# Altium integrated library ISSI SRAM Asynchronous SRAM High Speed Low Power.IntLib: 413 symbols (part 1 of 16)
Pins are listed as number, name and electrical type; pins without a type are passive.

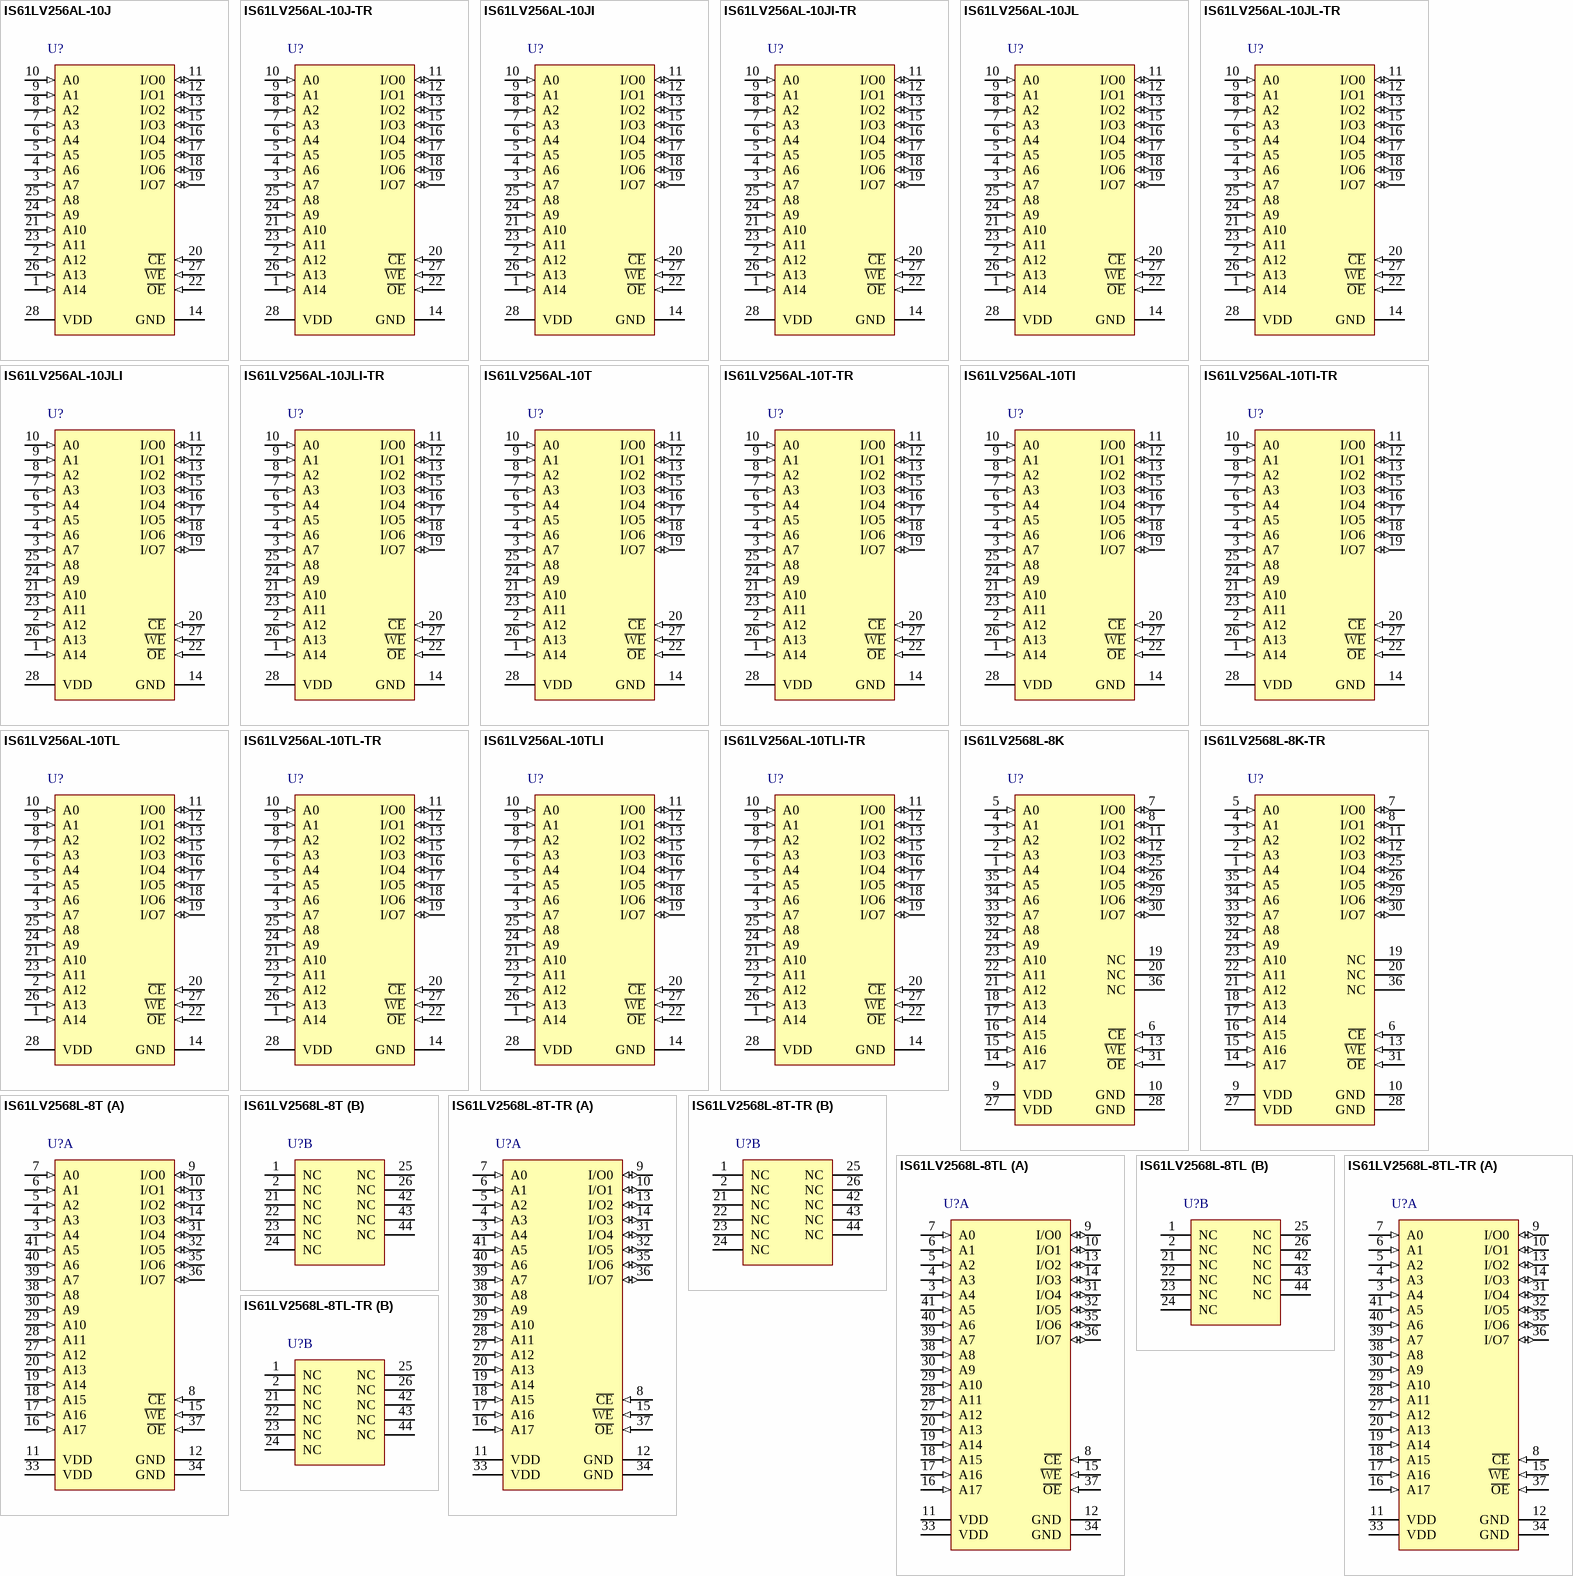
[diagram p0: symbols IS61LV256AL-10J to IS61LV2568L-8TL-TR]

## IS61LV256AL-10J
designator U?
256 K Low Voltage CMOS SRAM, 32 K x 8, 0 to 70 degC, 28-Pin SOJ (SOJ-28); Manufacturer: Integrated Silicon Solution Inc (ISSI); PartNumber: IS61LV256AL-10J; Density: 256K; Organization: 32K x 8; Packing: Tray / Tube; Speed (ns): 10
footprint ISSI-SOJ-28_A_N (SOJ, 28-Leads, Body 18.54x7.75mm, Pitch 1.27mm, IPC Medium Density)
pins: 1 A14 (in) "Address Inputs", 2 A12 (in) "Address Inputs", 3 A7 (in) "Address Inputs", 4 A6 (in) "Address Inputs", 5 A5 (in) "Address Inputs", 6 A4 (in) "Address Inputs", 7 A3 (in) "Address Inputs", 8 A2 (in) "Address Inputs", 9 A1 (in) "Address Inputs", 10 A0 (in) "Address Inputs", 11 I/O0 (io) "Input/Output", 12 I/O1 (io) "Input/Output", 13 I/O2 (io) "Input/Output", 14 GND (power) "Ground", 15 I/O3 (io) "Input/Output", 16 I/O4 (io) "Input/Output", 17 I/O5 (io) "Input/Output", 18 I/O6 (io) "Input/Output", 19 I/O7 (io) "Input/Output", 20 ~{CE} (in) "Chip Enable Input", 21 A10 (in) "Address Inputs", 22 ~{OE} (in) "Output Enable Input", 23 A11 (in) "Address Inputs", 24 A9 (in) "Address Inputs", 25 A8 (in) "Address Inputs", 26 A13 (in) "Address Inputs", 27 ~{WE} (in) "Write Enable Input", 28 VDD (power) "Power"

## IS61LV256AL-10J-TR
designator U?
256 K Low Voltage CMOS SRAM, 32 K x 8, 0 to 70 degC, 28-Pin SOJ (SOJ-28_A); Manufacturer: Integrated Silicon Solution Inc (ISSI); PartNumber: IS61LV256AL-10J-TR; Density: 256K; Organization: 32K x 8; Packing: Tape & Reel; Speed (ns): 10
footprint ISSI-SOJ-28_A_N (SOJ, 28-Leads, Body 18.54x7.75mm, Pitch 1.27mm, IPC Medium Density)
pins: 1 A14 (in) "Address Inputs", 2 A12 (in) "Address Inputs", 3 A7 (in) "Address Inputs", 4 A6 (in) "Address Inputs", 5 A5 (in) "Address Inputs", 6 A4 (in) "Address Inputs", 7 A3 (in) "Address Inputs", 8 A2 (in) "Address Inputs", 9 A1 (in) "Address Inputs", 10 A0 (in) "Address Inputs", 11 I/O0 (io) "Input/Output", 12 I/O1 (io) "Input/Output", 13 I/O2 (io) "Input/Output", 14 GND (power) "Ground", 15 I/O3 (io) "Input/Output", 16 I/O4 (io) "Input/Output", 17 I/O5 (io) "Input/Output", 18 I/O6 (io) "Input/Output", 19 I/O7 (io) "Input/Output", 20 ~{CE} (in) "Chip Enable Input", 21 A10 (in) "Address Inputs", 22 ~{OE} (in) "Output Enable Input", 23 A11 (in) "Address Inputs", 24 A9 (in) "Address Inputs", 25 A8 (in) "Address Inputs", 26 A13 (in) "Address Inputs", 27 ~{WE} (in) "Write Enable Input", 28 VDD (power) "Power"

## IS61LV256AL-10JI
designator U?
256 K Low Voltage CMOS SRAM, 32 K x 8, -40 to 85 degC, 28-Pin SOJ (SOJ-28); Manufacturer: Integrated Silicon Solution Inc (ISSI); PartNumber: IS61LV256AL-10JI; Density: 256K; Organization: 32K x 8; Packing: Tray / Tube; Speed (ns): 10
footprint ISSI-SOJ-28_A_N (SOJ, 28-Leads, Body 18.54x7.75mm, Pitch 1.27mm, IPC Medium Density)
pins: 1 A14 (in) "Address Inputs", 2 A12 (in) "Address Inputs", 3 A7 (in) "Address Inputs", 4 A6 (in) "Address Inputs", 5 A5 (in) "Address Inputs", 6 A4 (in) "Address Inputs", 7 A3 (in) "Address Inputs", 8 A2 (in) "Address Inputs", 9 A1 (in) "Address Inputs", 10 A0 (in) "Address Inputs", 11 I/O0 (io) "Input/Output", 12 I/O1 (io) "Input/Output", 13 I/O2 (io) "Input/Output", 14 GND (power) "Ground", 15 I/O3 (io) "Input/Output", 16 I/O4 (io) "Input/Output", 17 I/O5 (io) "Input/Output", 18 I/O6 (io) "Input/Output", 19 I/O7 (io) "Input/Output", 20 ~{CE} (in) "Chip Enable Input", 21 A10 (in) "Address Inputs", 22 ~{OE} (in) "Output Enable Input", 23 A11 (in) "Address Inputs", 24 A9 (in) "Address Inputs", 25 A8 (in) "Address Inputs", 26 A13 (in) "Address Inputs", 27 ~{WE} (in) "Write Enable Input", 28 VDD (power) "Power"

## IS61LV256AL-10JI-TR
designator U?
256 K Low Voltage CMOS SRAM, 32 K x 8, -40 to 85 degC, 28-Pin SOJ (SOJ-28_A); Manufacturer: Integrated Silicon Solution Inc (ISSI); PartNumber: IS61LV256AL-10JI-TR; Density: 256K; Organization: 32K x 8; Packing: Tape & Reel; Speed (ns): 10
footprint ISSI-SOJ-28_A_N (SOJ, 28-Leads, Body 18.54x7.75mm, Pitch 1.27mm, IPC Medium Density)
pins: 1 A14 (in) "Address Inputs", 2 A12 (in) "Address Inputs", 3 A7 (in) "Address Inputs", 4 A6 (in) "Address Inputs", 5 A5 (in) "Address Inputs", 6 A4 (in) "Address Inputs", 7 A3 (in) "Address Inputs", 8 A2 (in) "Address Inputs", 9 A1 (in) "Address Inputs", 10 A0 (in) "Address Inputs", 11 I/O0 (io) "Input/Output", 12 I/O1 (io) "Input/Output", 13 I/O2 (io) "Input/Output", 14 GND (power) "Ground", 15 I/O3 (io) "Input/Output", 16 I/O4 (io) "Input/Output", 17 I/O5 (io) "Input/Output", 18 I/O6 (io) "Input/Output", 19 I/O7 (io) "Input/Output", 20 ~{CE} (in) "Chip Enable Input", 21 A10 (in) "Address Inputs", 22 ~{OE} (in) "Output Enable Input", 23 A11 (in) "Address Inputs", 24 A9 (in) "Address Inputs", 25 A8 (in) "Address Inputs", 26 A13 (in) "Address Inputs", 27 ~{WE} (in) "Write Enable Input", 28 VDD (power) "Power"

## IS61LV256AL-10JL
designator U?
256 K Low Voltage CMOS SRAM, 32 K x 8, 0 to 70 degC, 28-Pin SOJ (SOJ-28), Pb-Free; Manufacturer: Integrated Silicon Solution Inc (ISSI); PartNumber: IS61LV256AL-10JL; Density: 256K; Organization: 32K x 8; Packing: Tray / Tube; Speed (ns): 10
footprint ISSI-SOJ-28_A_N (SOJ, 28-Leads, Body 18.54x7.75mm, Pitch 1.27mm, IPC Medium Density)
pins: 1 A14 (in) "Address Inputs", 2 A12 (in) "Address Inputs", 3 A7 (in) "Address Inputs", 4 A6 (in) "Address Inputs", 5 A5 (in) "Address Inputs", 6 A4 (in) "Address Inputs", 7 A3 (in) "Address Inputs", 8 A2 (in) "Address Inputs", 9 A1 (in) "Address Inputs", 10 A0 (in) "Address Inputs", 11 I/O0 (io) "Input/Output", 12 I/O1 (io) "Input/Output", 13 I/O2 (io) "Input/Output", 14 GND (power) "Ground", 15 I/O3 (io) "Input/Output", 16 I/O4 (io) "Input/Output", 17 I/O5 (io) "Input/Output", 18 I/O6 (io) "Input/Output", 19 I/O7 (io) "Input/Output", 20 ~{CE} (in) "Chip Enable Input", 21 A10 (in) "Address Inputs", 22 ~{OE} (in) "Output Enable Input", 23 A11 (in) "Address Inputs", 24 A9 (in) "Address Inputs", 25 A8 (in) "Address Inputs", 26 A13 (in) "Address Inputs", 27 ~{WE} (in) "Write Enable Input", 28 VDD (power) "Power"

## IS61LV256AL-10JL-TR
designator U?
256 K Low Voltage CMOS SRAM, 32 K x 8, 0 to 70 degC, 28-Pin SOJ (SOJ-28_A), Pb-Free; Manufacturer: Integrated Silicon Solution Inc (ISSI); PartNumber: IS61LV256AL-10JL-TR; Density: 256K; Organization: 32K x 8; Packing: Tape & Reel; Speed (ns): 10
footprint ISSI-SOJ-28_A_N (SOJ, 28-Leads, Body 18.54x7.75mm, Pitch 1.27mm, IPC Medium Density)
pins: 1 A14 (in) "Address Inputs", 2 A12 (in) "Address Inputs", 3 A7 (in) "Address Inputs", 4 A6 (in) "Address Inputs", 5 A5 (in) "Address Inputs", 6 A4 (in) "Address Inputs", 7 A3 (in) "Address Inputs", 8 A2 (in) "Address Inputs", 9 A1 (in) "Address Inputs", 10 A0 (in) "Address Inputs", 11 I/O0 (io) "Input/Output", 12 I/O1 (io) "Input/Output", 13 I/O2 (io) "Input/Output", 14 GND (power) "Ground", 15 I/O3 (io) "Input/Output", 16 I/O4 (io) "Input/Output", 17 I/O5 (io) "Input/Output", 18 I/O6 (io) "Input/Output", 19 I/O7 (io) "Input/Output", 20 ~{CE} (in) "Chip Enable Input", 21 A10 (in) "Address Inputs", 22 ~{OE} (in) "Output Enable Input", 23 A11 (in) "Address Inputs", 24 A9 (in) "Address Inputs", 25 A8 (in) "Address Inputs", 26 A13 (in) "Address Inputs", 27 ~{WE} (in) "Write Enable Input", 28 VDD (power) "Power"

## IS61LV256AL-10JLI
designator U?
256 K Low Voltage CMOS SRAM, 32 K x 8, -40 to 85 degC, 28-Pin SOJ (SOJ-28), Pb-Free; Manufacturer: Integrated Silicon Solution Inc (ISSI); PartNumber: IS61LV256AL-10JLI; Density: 256K; Organization: 32K x 8; Packing: Tray / Tube; Speed (ns): 10
footprint ISSI-SOJ-28_A_N (SOJ, 28-Leads, Body 18.54x7.75mm, Pitch 1.27mm, IPC Medium Density)
pins: 1 A14 (in) "Address Inputs", 2 A12 (in) "Address Inputs", 3 A7 (in) "Address Inputs", 4 A6 (in) "Address Inputs", 5 A5 (in) "Address Inputs", 6 A4 (in) "Address Inputs", 7 A3 (in) "Address Inputs", 8 A2 (in) "Address Inputs", 9 A1 (in) "Address Inputs", 10 A0 (in) "Address Inputs", 11 I/O0 (io) "Input/Output", 12 I/O1 (io) "Input/Output", 13 I/O2 (io) "Input/Output", 14 GND (power) "Ground", 15 I/O3 (io) "Input/Output", 16 I/O4 (io) "Input/Output", 17 I/O5 (io) "Input/Output", 18 I/O6 (io) "Input/Output", 19 I/O7 (io) "Input/Output", 20 ~{CE} (in) "Chip Enable Input", 21 A10 (in) "Address Inputs", 22 ~{OE} (in) "Output Enable Input", 23 A11 (in) "Address Inputs", 24 A9 (in) "Address Inputs", 25 A8 (in) "Address Inputs", 26 A13 (in) "Address Inputs", 27 ~{WE} (in) "Write Enable Input", 28 VDD (power) "Power"

## IS61LV256AL-10JLI-TR
designator U?
256 K Low Voltage CMOS SRAM, 32 K x 8, -40 to 85 degC, 28-Pin SOJ (SOJ-28_A), Pb-Free; Manufacturer: Integrated Silicon Solution Inc (ISSI); PartNumber: IS61LV256AL-10JLI-TR; Density: 256K; Organization: 32K x 8; Packing: Tape & Reel; Speed (ns): 10
footprint ISSI-SOJ-28_A_N (SOJ, 28-Leads, Body 18.54x7.75mm, Pitch 1.27mm, IPC Medium Density)
pins: 1 A14 (in) "Address Inputs", 2 A12 (in) "Address Inputs", 3 A7 (in) "Address Inputs", 4 A6 (in) "Address Inputs", 5 A5 (in) "Address Inputs", 6 A4 (in) "Address Inputs", 7 A3 (in) "Address Inputs", 8 A2 (in) "Address Inputs", 9 A1 (in) "Address Inputs", 10 A0 (in) "Address Inputs", 11 I/O0 (io) "Input/Output", 12 I/O1 (io) "Input/Output", 13 I/O2 (io) "Input/Output", 14 GND (power) "Ground", 15 I/O3 (io) "Input/Output", 16 I/O4 (io) "Input/Output", 17 I/O5 (io) "Input/Output", 18 I/O6 (io) "Input/Output", 19 I/O7 (io) "Input/Output", 20 ~{CE} (in) "Chip Enable Input", 21 A10 (in) "Address Inputs", 22 ~{OE} (in) "Output Enable Input", 23 A11 (in) "Address Inputs", 24 A9 (in) "Address Inputs", 25 A8 (in) "Address Inputs", 26 A13 (in) "Address Inputs", 27 ~{WE} (in) "Write Enable Input", 28 VDD (power) "Power"

## IS61LV256AL-10T
designator U?
256 K Low Voltage CMOS SRAM, 32 K x 8, 0 to 70 degC, 28-Pin SOP (TSOP-1-28); Manufacturer: Integrated Silicon Solution Inc (ISSI); PartNumber: IS61LV256AL-10T; Density: 256K; Organization: 32K x 8; Packing: Tray / Tube; Speed (ns): 10
footprint ISSI-TSOP-1-28-8000X13400DE_N (SOP, 28-Leads, Body 11.9x8.1mm, Pitch 0.55mm, IPC Medium Density)
pins: 1 A14 (in) "Address Input", 2 A12 (in) "Address Input", 3 A7 (in) "Address Input", 4 A6 (in) "Address Input", 5 A5 (in) "Address Input", 6 A4 (in) "Address Input", 7 A3 (in) "Address Input", 8 A2 (in) "Address Input", 9 A1 (in) "Address Input", 10 A0 (in) "Address Input", 11 I/O0 (io) "Input/Output", 12 I/O1 (io) "Input/Output", 13 I/O2 (io) "Input/Output", 14 GND (power) "Ground", 15 I/O3 (io) "Input/Output", 16 I/O4 (io) "Input/Output", 17 I/O5 (io) "Input/Output", 18 I/O6 (io) "Input/Output", 19 I/O7 (io) "Input/Output", 20 ~{CE} (in) "Chip Enable Input", 21 A10 (in) "Address Input", 22 ~{OE} (in) "Output Enable Input", 23 A11 (in) "Address Input", 24 A9 (in) "Address Input", 25 A8 (in) "Address Input", 26 A13 (in) "Address Input", 27 ~{WE} (in) "Write Enable Input", 28 VDD (power) "Power"

## IS61LV256AL-10T-TR
designator U?
256 K Low Voltage CMOS SRAM, 32 K x 8, 0 to 70 degC, 28-Pin SOP (TSOP-1-28); Manufacturer: Integrated Silicon Solution Inc (ISSI); PartNumber: IS61LV256AL-10T-TR; Density: 256K; Organization: 32K x 8; Packing: Tape & Reel; Speed (ns): 10
footprint ISSI-TSOP-1-28-8000X13400DE_N (SOP, 28-Leads, Body 11.9x8.1mm, Pitch 0.55mm, IPC Medium Density)
pins: 1 A14 (in) "Address Input", 2 A12 (in) "Address Input", 3 A7 (in) "Address Input", 4 A6 (in) "Address Input", 5 A5 (in) "Address Input", 6 A4 (in) "Address Input", 7 A3 (in) "Address Input", 8 A2 (in) "Address Input", 9 A1 (in) "Address Input", 10 A0 (in) "Address Input", 11 I/O0 (io) "Input/Output", 12 I/O1 (io) "Input/Output", 13 I/O2 (io) "Input/Output", 14 GND (power) "Ground", 15 I/O3 (io) "Input/Output", 16 I/O4 (io) "Input/Output", 17 I/O5 (io) "Input/Output", 18 I/O6 (io) "Input/Output", 19 I/O7 (io) "Input/Output", 20 ~{CE} (in) "Chip Enable Input", 21 A10 (in) "Address Input", 22 ~{OE} (in) "Output Enable Input", 23 A11 (in) "Address Input", 24 A9 (in) "Address Input", 25 A8 (in) "Address Input", 26 A13 (in) "Address Input", 27 ~{WE} (in) "Write Enable Input", 28 VDD (power) "Power"

## IS61LV256AL-10TI
designator U?
256 K Low Voltage CMOS SRAM, 32 K x 8, -40 to 85 degC, 28-Pin SOP (TSOP-1-28); Manufacturer: Integrated Silicon Solution Inc (ISSI); PartNumber: IS61LV256AL-10TI; Density: 256K; Organization: 32K x 8; Packing: Tray / Tube; Speed (ns): 10
footprint ISSI-TSOP-1-28-8000X13400DE_N (SOP, 28-Leads, Body 11.9x8.1mm, Pitch 0.55mm, IPC Medium Density)
pins: 1 A14 (in) "Address Input", 2 A12 (in) "Address Input", 3 A7 (in) "Address Input", 4 A6 (in) "Address Input", 5 A5 (in) "Address Input", 6 A4 (in) "Address Input", 7 A3 (in) "Address Input", 8 A2 (in) "Address Input", 9 A1 (in) "Address Input", 10 A0 (in) "Address Input", 11 I/O0 (io) "Input/Output", 12 I/O1 (io) "Input/Output", 13 I/O2 (io) "Input/Output", 14 GND (power) "Ground", 15 I/O3 (io) "Input/Output", 16 I/O4 (io) "Input/Output", 17 I/O5 (io) "Input/Output", 18 I/O6 (io) "Input/Output", 19 I/O7 (io) "Input/Output", 20 ~{CE} (in) "Chip Enable Input", 21 A10 (in) "Address Input", 22 ~{OE} (in) "Output Enable Input", 23 A11 (in) "Address Input", 24 A9 (in) "Address Input", 25 A8 (in) "Address Input", 26 A13 (in) "Address Input", 27 ~{WE} (in) "Write Enable Input", 28 VDD (power) "Power"

## IS61LV256AL-10TI-TR
designator U?
256 K Low Voltage CMOS SRAM, 32 K x 8, -40 to 85 degC, 28-Pin SOP (TSOP-1-28); Manufacturer: Integrated Silicon Solution Inc (ISSI); PartNumber: IS61LV256AL-10TI-TR; Density: 256K; Organization: 32K x 8; Packing: Tape & Reel; Speed (ns): 10
footprint ISSI-TSOP-1-28-8000X13400DE_N (SOP, 28-Leads, Body 11.9x8.1mm, Pitch 0.55mm, IPC Medium Density)
pins: 1 A14 (in) "Address Input", 2 A12 (in) "Address Input", 3 A7 (in) "Address Input", 4 A6 (in) "Address Input", 5 A5 (in) "Address Input", 6 A4 (in) "Address Input", 7 A3 (in) "Address Input", 8 A2 (in) "Address Input", 9 A1 (in) "Address Input", 10 A0 (in) "Address Input", 11 I/O0 (io) "Input/Output", 12 I/O1 (io) "Input/Output", 13 I/O2 (io) "Input/Output", 14 GND (power) "Ground", 15 I/O3 (io) "Input/Output", 16 I/O4 (io) "Input/Output", 17 I/O5 (io) "Input/Output", 18 I/O6 (io) "Input/Output", 19 I/O7 (io) "Input/Output", 20 ~{CE} (in) "Chip Enable Input", 21 A10 (in) "Address Input", 22 ~{OE} (in) "Output Enable Input", 23 A11 (in) "Address Input", 24 A9 (in) "Address Input", 25 A8 (in) "Address Input", 26 A13 (in) "Address Input", 27 ~{WE} (in) "Write Enable Input", 28 VDD (power) "Power"

## IS61LV256AL-10TL
designator U?
256 K Low Voltage CMOS SRAM, 32 K x 8, 0 to 70 degC, 28-Pin SOP (TSOP-1-28), Pb-Free; Manufacturer: Integrated Silicon Solution Inc (ISSI); PartNumber: IS61LV256AL-10TL; Density: 256K; Organization: 32K x 8; Packing: Tray / Tube; Speed (ns): 10
footprint ISSI-TSOP-1-28-8000X13400DE_N (SOP, 28-Leads, Body 11.9x8.1mm, Pitch 0.55mm, IPC Medium Density)
pins: 1 A14 (in) "Address Input", 2 A12 (in) "Address Input", 3 A7 (in) "Address Input", 4 A6 (in) "Address Input", 5 A5 (in) "Address Input", 6 A4 (in) "Address Input", 7 A3 (in) "Address Input", 8 A2 (in) "Address Input", 9 A1 (in) "Address Input", 10 A0 (in) "Address Input", 11 I/O0 (io) "Input/Output", 12 I/O1 (io) "Input/Output", 13 I/O2 (io) "Input/Output", 14 GND (power) "Ground", 15 I/O3 (io) "Input/Output", 16 I/O4 (io) "Input/Output", 17 I/O5 (io) "Input/Output", 18 I/O6 (io) "Input/Output", 19 I/O7 (io) "Input/Output", 20 ~{CE} (in) "Chip Enable Input", 21 A10 (in) "Address Input", 22 ~{OE} (in) "Output Enable Input", 23 A11 (in) "Address Input", 24 A9 (in) "Address Input", 25 A8 (in) "Address Input", 26 A13 (in) "Address Input", 27 ~{WE} (in) "Write Enable Input", 28 VDD (power) "Power"

## IS61LV256AL-10TL-TR
designator U?
256 K Low Voltage CMOS SRAM, 32 K x 8, 0 to 70 degC, 28-Pin SOP (TSOP-1-28), Pb-Free; Manufacturer: Integrated Silicon Solution Inc (ISSI); PartNumber: IS61LV256AL-10TL-TR; Density: 256K; Organization: 32K x 8; Packing: Tape & Reel; Speed (ns): 10
footprint ISSI-TSOP-1-28-8000X13400DE_N (SOP, 28-Leads, Body 11.9x8.1mm, Pitch 0.55mm, IPC Medium Density)
pins: 1 A14 (in) "Address Input", 2 A12 (in) "Address Input", 3 A7 (in) "Address Input", 4 A6 (in) "Address Input", 5 A5 (in) "Address Input", 6 A4 (in) "Address Input", 7 A3 (in) "Address Input", 8 A2 (in) "Address Input", 9 A1 (in) "Address Input", 10 A0 (in) "Address Input", 11 I/O0 (io) "Input/Output", 12 I/O1 (io) "Input/Output", 13 I/O2 (io) "Input/Output", 14 GND (power) "Ground", 15 I/O3 (io) "Input/Output", 16 I/O4 (io) "Input/Output", 17 I/O5 (io) "Input/Output", 18 I/O6 (io) "Input/Output", 19 I/O7 (io) "Input/Output", 20 ~{CE} (in) "Chip Enable Input", 21 A10 (in) "Address Input", 22 ~{OE} (in) "Output Enable Input", 23 A11 (in) "Address Input", 24 A9 (in) "Address Input", 25 A8 (in) "Address Input", 26 A13 (in) "Address Input", 27 ~{WE} (in) "Write Enable Input", 28 VDD (power) "Power"

## IS61LV256AL-10TLI
designator U?
256 K Low Voltage CMOS SRAM, 32 K x 8, -40 to 85 degC, 28-Pin SOP (TSOP-1-28), Pb-Free; Manufacturer: Integrated Silicon Solution Inc (ISSI); PartNumber: IS61LV256AL-10TLI; Density: 256K; Organization: 32K x 8; Packing: Tray / Tube; Speed (ns): 10
footprint ISSI-TSOP-1-28-8000X13400DE_N (SOP, 28-Leads, Body 11.9x8.1mm, Pitch 0.55mm, IPC Medium Density)
pins: 1 A14 (in) "Address Input", 2 A12 (in) "Address Input", 3 A7 (in) "Address Input", 4 A6 (in) "Address Input", 5 A5 (in) "Address Input", 6 A4 (in) "Address Input", 7 A3 (in) "Address Input", 8 A2 (in) "Address Input", 9 A1 (in) "Address Input", 10 A0 (in) "Address Input", 11 I/O0 (io) "Input/Output", 12 I/O1 (io) "Input/Output", 13 I/O2 (io) "Input/Output", 14 GND (power) "Ground", 15 I/O3 (io) "Input/Output", 16 I/O4 (io) "Input/Output", 17 I/O5 (io) "Input/Output", 18 I/O6 (io) "Input/Output", 19 I/O7 (io) "Input/Output", 20 ~{CE} (in) "Chip Enable Input", 21 A10 (in) "Address Input", 22 ~{OE} (in) "Output Enable Input", 23 A11 (in) "Address Input", 24 A9 (in) "Address Input", 25 A8 (in) "Address Input", 26 A13 (in) "Address Input", 27 ~{WE} (in) "Write Enable Input", 28 VDD (power) "Power"

## IS61LV256AL-10TLI-TR
designator U?
256 K Low Voltage CMOS SRAM, 32 K x 8, -40 to 85 degC, 28-Pin SOP (TSOP-1-28), Pb-Free; Manufacturer: Integrated Silicon Solution Inc (ISSI); PartNumber: IS61LV256AL-10TLI-TR; Density: 256K; Organization: 32K x 8; Packing: Tape & Reel; Speed (ns): 10
footprint ISSI-TSOP-1-28-8000X13400DE_N (SOP, 28-Leads, Body 11.9x8.1mm, Pitch 0.55mm, IPC Medium Density)
pins: 1 A14 (in) "Address Input", 2 A12 (in) "Address Input", 3 A7 (in) "Address Input", 4 A6 (in) "Address Input", 5 A5 (in) "Address Input", 6 A4 (in) "Address Input", 7 A3 (in) "Address Input", 8 A2 (in) "Address Input", 9 A1 (in) "Address Input", 10 A0 (in) "Address Input", 11 I/O0 (io) "Input/Output", 12 I/O1 (io) "Input/Output", 13 I/O2 (io) "Input/Output", 14 GND (power) "Ground", 15 I/O3 (io) "Input/Output", 16 I/O4 (io) "Input/Output", 17 I/O5 (io) "Input/Output", 18 I/O6 (io) "Input/Output", 19 I/O7 (io) "Input/Output", 20 ~{CE} (in) "Chip Enable Input", 21 A10 (in) "Address Input", 22 ~{OE} (in) "Output Enable Input", 23 A11 (in) "Address Input", 24 A9 (in) "Address Input", 25 A8 (in) "Address Input", 26 A13 (in) "Address Input", 27 ~{WE} (in) "Write Enable Input", 28 VDD (power) "Power"

## IS61LV2568L-8K
designator U?
2 M High Speed CMOS SRAM, 256 K x 8, 0 to 70 degC, 36-Pin SOJ (SOJ-36); Manufacturer: Integrated Silicon Solution Inc (ISSI); PartNumber: IS61LV2568L-8K; Density: 2M; Organization: 256K x 8; Packing: Tray / Tube; Speed (ns): 8
footprint ISSI-SOJ-36_N (SOJ, 36-Leads, Body 23.62x10.29mm, Pitch 1.27mm, IPC Medium Density)
pins: 1 A4 (in) "Address Input", 2 A3 (in) "Address Input", 3 A2 (in) "Address Input", 4 A1 (in) "Address Input", 5 A0 (in) "Address Input", 6 ~{CE} (in) "Chip Enable Input", 7 I/O0 (io) "Bidirectional Port", 8 I/O1 (io) "Bidirectional Port", 9 VDD (power) "Power", 10 GND (power) "Ground", 11 I/O2 (io) "Bidirectional Port", 12 I/O3 (io) "Bidirectional Port", 13 ~{WE} (in) "Write Enable Input", 14 A17 (in) "Address Input", 15 A16 (in) "Address Input", 16 A15 (in) "Address Input", 17 A14 (in) "Address Input", 18 A13 (in) "Address Input", 19 NC "No Connection", 20 NC "No Connection", 21 A12 (in) "Address Input", 22 A11 (in) "Address Input", 23 A10 (in) "Address Input", 24 A9 (in) "Address Input", 25 I/O4 (io) "Bidirectional Port", 26 I/O5 (io) "Bidirectional Port", 27 VDD (power) "Power", 28 GND (power) "Ground", 29 I/O6 (io) "Bidirectional Port", 30 I/O7 (io) "Bidirectional Port", 31 ~{OE} (in) "Output Enable Input", 32 A8 (in) "Address Input", 33 A7 (in) "Address Input", 34 A6 (in) "Address Input", 35 A5 (in) "Address Input", 36 NC "No Connection"

## IS61LV2568L-8K-TR
designator U?
2 M High Speed CMOS SRAM, 256 K x 8, 0 to 70 degC, 36-Pin SOJ (SOJ-36); Manufacturer: Integrated Silicon Solution Inc (ISSI); PartNumber: IS61LV2568L-8K-TR; Density: 2M; Organization: 256K x 8; Packing: Tape & Reel; Speed (ns): 8
footprint ISSI-SOJ-36_N (SOJ, 36-Leads, Body 23.62x10.29mm, Pitch 1.27mm, IPC Medium Density)
pins: 1 A4 (in) "Address Input", 2 A3 (in) "Address Input", 3 A2 (in) "Address Input", 4 A1 (in) "Address Input", 5 A0 (in) "Address Input", 6 ~{CE} (in) "Chip Enable Input", 7 I/O0 (io) "Bidirectional Port", 8 I/O1 (io) "Bidirectional Port", 9 VDD (power) "Power", 10 GND (power) "Ground", 11 I/O2 (io) "Bidirectional Port", 12 I/O3 (io) "Bidirectional Port", 13 ~{WE} (in) "Write Enable Input", 14 A17 (in) "Address Input", 15 A16 (in) "Address Input", 16 A15 (in) "Address Input", 17 A14 (in) "Address Input", 18 A13 (in) "Address Input", 19 NC "No Connection", 20 NC "No Connection", 21 A12 (in) "Address Input", 22 A11 (in) "Address Input", 23 A10 (in) "Address Input", 24 A9 (in) "Address Input", 25 I/O4 (io) "Bidirectional Port", 26 I/O5 (io) "Bidirectional Port", 27 VDD (power) "Power", 28 GND (power) "Ground", 29 I/O6 (io) "Bidirectional Port", 30 I/O7 (io) "Bidirectional Port", 31 ~{OE} (in) "Output Enable Input", 32 A8 (in) "Address Input", 33 A7 (in) "Address Input", 34 A6 (in) "Address Input", 35 A5 (in) "Address Input", 36 NC "No Connection"

## IS61LV2568L-8T
designator U?
2 M High Speed CMOS SRAM, 256 K x 8, 0 to 70 degC, 44-Pin SOP (TSOP-2-44); Manufacturer: Integrated Silicon Solution Inc (ISSI); PartNumber: IS61LV2568L-8T; Density: 2M; Organization: 256K x 8; Packing: Tray / Tube; Speed (ns): 8
footprint ISSI-TSOP-2-44_N (SOP, 44-Leads, Body 18.5x10.3mm, Pitch 0.8mm, IPC Medium Density)
part A pins: 3 A4 (in) "Address Input", 4 A3 (in) "Address Input", 5 A2 (in) "Address Input", 6 A1 (in) "Address Input", 7 A0 (in) "Address Input", 8 ~{CE} (in) "Chip Enable Input", 9 I/O0 (io) "Bidirectional Port", 10 I/O1 (io) "Bidirectional Port", 11 VDD (power) "Power", 12 GND (power) "Ground", 13 I/O2 (io) "Bidirectional Port", 14 I/O3 (io) "Bidirectional Port", 15 ~{WE} (in) "Write Enable Input", 16 A17 (in) "Address Input", 17 A16 (in) "Address Input", 18 A15 (in) "Address Input", 19 A14 (in) "Address Input", 20 A13 (in) "Address Input", 27 A12 (in) "Address Input", 28 A11 (in) "Address Input", 29 A10 (in) "Address Input", 30 A9 (in) "Address Input", 31 I/O4 (io) "Bidirectional Port", 32 I/O5 (io) "Bidirectional Port", 33 VDD (power) "Power", 34 GND (power) "Ground", 35 I/O6 (io) "Bidirectional Port", 36 I/O7 (io) "Bidirectional Port", 37 ~{OE} (in) "Output Enable Input", 38 A8 (in) "Address Input", 39 A7 (in) "Address Input", 40 A6 (in) "Address Input", 41 A5 (in) "Address Input"
part B pins: 1 NC "No Connection", 2 NC "No Connection", 21 NC "No Connection", 22 NC "No Connection", 23 NC "No Connection", 24 NC "No Connection", 25 NC "No Connection", 26 NC "No Connection", 42 NC "No Connection", 43 NC "No Connection", 44 NC "No Connection"

## IS61LV2568L-8T-TR
designator U?
2 M High Speed CMOS SRAM, 256 K x 8, 0 to 70 degC, 44-Pin SOP (TSOP-2-44); Manufacturer: Integrated Silicon Solution Inc (ISSI); PartNumber: IS61LV2568L-8T-TR; Density: 2M; Organization: 256K x 8; Packing: Tape & Reel; Speed (ns): 8
footprint ISSI-TSOP-2-44_N (SOP, 44-Leads, Body 18.5x10.3mm, Pitch 0.8mm, IPC Medium Density)
part A pins: 3 A4 (in) "Address Input", 4 A3 (in) "Address Input", 5 A2 (in) "Address Input", 6 A1 (in) "Address Input", 7 A0 (in) "Address Input", 8 ~{CE} (in) "Chip Enable Input", 9 I/O0 (io) "Bidirectional Port", 10 I/O1 (io) "Bidirectional Port", 11 VDD (power) "Power", 12 GND (power) "Ground", 13 I/O2 (io) "Bidirectional Port", 14 I/O3 (io) "Bidirectional Port", 15 ~{WE} (in) "Write Enable Input", 16 A17 (in) "Address Input", 17 A16 (in) "Address Input", 18 A15 (in) "Address Input", 19 A14 (in) "Address Input", 20 A13 (in) "Address Input", 27 A12 (in) "Address Input", 28 A11 (in) "Address Input", 29 A10 (in) "Address Input", 30 A9 (in) "Address Input", 31 I/O4 (io) "Bidirectional Port", 32 I/O5 (io) "Bidirectional Port", 33 VDD (power) "Power", 34 GND (power) "Ground", 35 I/O6 (io) "Bidirectional Port", 36 I/O7 (io) "Bidirectional Port", 37 ~{OE} (in) "Output Enable Input", 38 A8 (in) "Address Input", 39 A7 (in) "Address Input", 40 A6 (in) "Address Input", 41 A5 (in) "Address Input"
part B pins: 1 NC "No Connection", 2 NC "No Connection", 21 NC "No Connection", 22 NC "No Connection", 23 NC "No Connection", 24 NC "No Connection", 25 NC "No Connection", 26 NC "No Connection", 42 NC "No Connection", 43 NC "No Connection", 44 NC "No Connection"

## IS61LV2568L-8TL
designator U?
2 M High Speed CMOS SRAM, 256 K x 8, 0 to 70 degC, 44-Pin SOP (TSOP-2-44), Pb-Free; Manufacturer: Integrated Silicon Solution Inc (ISSI); PartNumber: IS61LV2568L-8TL; Density: 2M; Organization: 256K x 8; Packing: Tray / Tube; Speed (ns): 8
footprint ISSI-TSOP-2-44_N (SOP, 44-Leads, Body 18.5x10.3mm, Pitch 0.8mm, IPC Medium Density)
part A pins: 3 A4 (in) "Address Input", 4 A3 (in) "Address Input", 5 A2 (in) "Address Input", 6 A1 (in) "Address Input", 7 A0 (in) "Address Input", 8 ~{CE} (in) "Chip Enable Input", 9 I/O0 (io) "Bidirectional Port", 10 I/O1 (io) "Bidirectional Port", 11 VDD (power) "Power", 12 GND (power) "Ground", 13 I/O2 (io) "Bidirectional Port", 14 I/O3 (io) "Bidirectional Port", 15 ~{WE} (in) "Write Enable Input", 16 A17 (in) "Address Input", 17 A16 (in) "Address Input", 18 A15 (in) "Address Input", 19 A14 (in) "Address Input", 20 A13 (in) "Address Input", 27 A12 (in) "Address Input", 28 A11 (in) "Address Input", 29 A10 (in) "Address Input", 30 A9 (in) "Address Input", 31 I/O4 (io) "Bidirectional Port", 32 I/O5 (io) "Bidirectional Port", 33 VDD (power) "Power", 34 GND (power) "Ground", 35 I/O6 (io) "Bidirectional Port", 36 I/O7 (io) "Bidirectional Port", 37 ~{OE} (in) "Output Enable Input", 38 A8 (in) "Address Input", 39 A7 (in) "Address Input", 40 A6 (in) "Address Input", 41 A5 (in) "Address Input"
part B pins: 1 NC "No Connection", 2 NC "No Connection", 21 NC "No Connection", 22 NC "No Connection", 23 NC "No Connection", 24 NC "No Connection", 25 NC "No Connection", 26 NC "No Connection", 42 NC "No Connection", 43 NC "No Connection", 44 NC "No Connection"

## IS61LV2568L-8TL-TR
designator U?
2 M High Speed CMOS SRAM, 256 K x 8, 0 to 70 degC, 44-Pin SOP (TSOP-2-44), Pb-Free; Manufacturer: Integrated Silicon Solution Inc (ISSI); PartNumber: IS61LV2568L-8TL-TR; Density: 2M; Organization: 256K x 8; Packing: Tape & Reel; Speed (ns): 8
footprint ISSI-TSOP-2-44_N (SOP, 44-Leads, Body 18.5x10.3mm, Pitch 0.8mm, IPC Medium Density)
part A pins: 3 A4 (in) "Address Input", 4 A3 (in) "Address Input", 5 A2 (in) "Address Input", 6 A1 (in) "Address Input", 7 A0 (in) "Address Input", 8 ~{CE} (in) "Chip Enable Input", 9 I/O0 (io) "Bidirectional Port", 10 I/O1 (io) "Bidirectional Port", 11 VDD (power) "Power", 12 GND (power) "Ground", 13 I/O2 (io) "Bidirectional Port", 14 I/O3 (io) "Bidirectional Port", 15 ~{WE} (in) "Write Enable Input", 16 A17 (in) "Address Input", 17 A16 (in) "Address Input", 18 A15 (in) "Address Input", 19 A14 (in) "Address Input", 20 A13 (in) "Address Input", 27 A12 (in) "Address Input", 28 A11 (in) "Address Input", 29 A10 (in) "Address Input", 30 A9 (in) "Address Input", 31 I/O4 (io) "Bidirectional Port", 32 I/O5 (io) "Bidirectional Port", 33 VDD (power) "Power", 34 GND (power) "Ground", 35 I/O6 (io) "Bidirectional Port", 36 I/O7 (io) "Bidirectional Port", 37 ~{OE} (in) "Output Enable Input", 38 A8 (in) "Address Input", 39 A7 (in) "Address Input", 40 A6 (in) "Address Input", 41 A5 (in) "Address Input"
part B pins: 1 NC "No Connection", 2 NC "No Connection", 21 NC "No Connection", 22 NC "No Connection", 23 NC "No Connection", 24 NC "No Connection", 25 NC "No Connection", 26 NC "No Connection", 42 NC "No Connection", 43 NC "No Connection", 44 NC "No Connection"

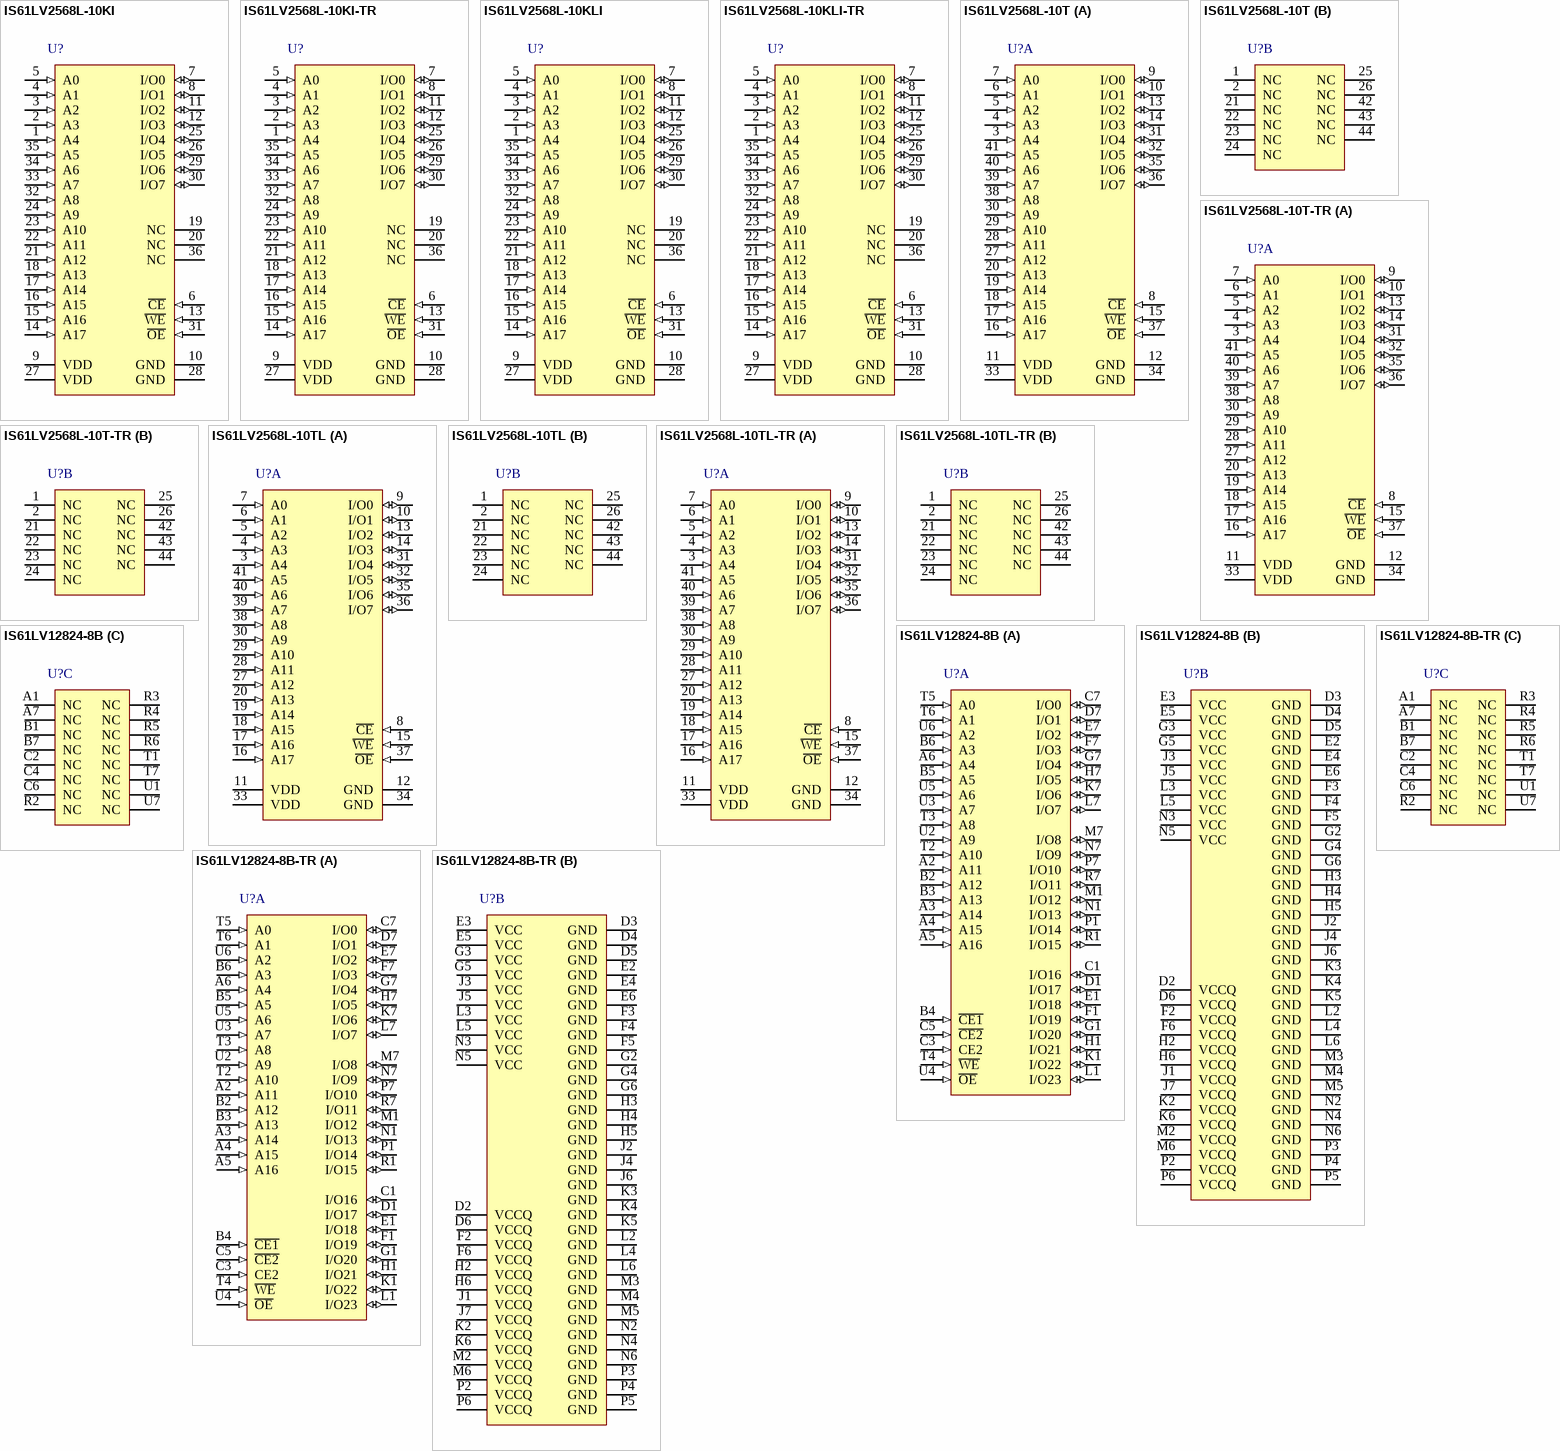
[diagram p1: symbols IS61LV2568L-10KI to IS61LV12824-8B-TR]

## IS61LV2568L-10KI
designator U?
2 M High Speed CMOS SRAM, 256 K x 8, -40 to 85 degC, 36-Pin SOJ (SOJ-36); Manufacturer: Integrated Silicon Solution Inc (ISSI); PartNumber: IS61LV2568L-10KI; Density: 2M; Organization: 256K x 8; Packing: Tray / Tube; Speed (ns): 10
footprint ISSI-SOJ-36_N (SOJ, 36-Leads, Body 23.62x10.29mm, Pitch 1.27mm, IPC Medium Density)
pins: 1 A4 (in) "Address Input", 2 A3 (in) "Address Input", 3 A2 (in) "Address Input", 4 A1 (in) "Address Input", 5 A0 (in) "Address Input", 6 ~{CE} (in) "Chip Enable Input", 7 I/O0 (io) "Bidirectional Port", 8 I/O1 (io) "Bidirectional Port", 9 VDD (power) "Power", 10 GND (power) "Ground", 11 I/O2 (io) "Bidirectional Port", 12 I/O3 (io) "Bidirectional Port", 13 ~{WE} (in) "Write Enable Input", 14 A17 (in) "Address Input", 15 A16 (in) "Address Input", 16 A15 (in) "Address Input", 17 A14 (in) "Address Input", 18 A13 (in) "Address Input", 19 NC "No Connection", 20 NC "No Connection", 21 A12 (in) "Address Input", 22 A11 (in) "Address Input", 23 A10 (in) "Address Input", 24 A9 (in) "Address Input", 25 I/O4 (io) "Bidirectional Port", 26 I/O5 (io) "Bidirectional Port", 27 VDD (power) "Power", 28 GND (power) "Ground", 29 I/O6 (io) "Bidirectional Port", 30 I/O7 (io) "Bidirectional Port", 31 ~{OE} (in) "Output Enable Input", 32 A8 (in) "Address Input", 33 A7 (in) "Address Input", 34 A6 (in) "Address Input", 35 A5 (in) "Address Input", 36 NC "No Connection"

## IS61LV2568L-10KI-TR
designator U?
2 M High Speed CMOS SRAM, 256 K x 8, -40 to 85 degC, 36-Pin SOJ (SOJ-36); Manufacturer: Integrated Silicon Solution Inc (ISSI); PartNumber: IS61LV2568L-10KI-TR; Density: 2M; Organization: 256K x 8; Packing: Tape & Reel; Speed (ns): 10
footprint ISSI-SOJ-36_N (SOJ, 36-Leads, Body 23.62x10.29mm, Pitch 1.27mm, IPC Medium Density)
pins: 1 A4 (in) "Address Input", 2 A3 (in) "Address Input", 3 A2 (in) "Address Input", 4 A1 (in) "Address Input", 5 A0 (in) "Address Input", 6 ~{CE} (in) "Chip Enable Input", 7 I/O0 (io) "Bidirectional Port", 8 I/O1 (io) "Bidirectional Port", 9 VDD (power) "Power", 10 GND (power) "Ground", 11 I/O2 (io) "Bidirectional Port", 12 I/O3 (io) "Bidirectional Port", 13 ~{WE} (in) "Write Enable Input", 14 A17 (in) "Address Input", 15 A16 (in) "Address Input", 16 A15 (in) "Address Input", 17 A14 (in) "Address Input", 18 A13 (in) "Address Input", 19 NC "No Connection", 20 NC "No Connection", 21 A12 (in) "Address Input", 22 A11 (in) "Address Input", 23 A10 (in) "Address Input", 24 A9 (in) "Address Input", 25 I/O4 (io) "Bidirectional Port", 26 I/O5 (io) "Bidirectional Port", 27 VDD (power) "Power", 28 GND (power) "Ground", 29 I/O6 (io) "Bidirectional Port", 30 I/O7 (io) "Bidirectional Port", 31 ~{OE} (in) "Output Enable Input", 32 A8 (in) "Address Input", 33 A7 (in) "Address Input", 34 A6 (in) "Address Input", 35 A5 (in) "Address Input", 36 NC "No Connection"

## IS61LV2568L-10KLI
designator U?
2 M High Speed CMOS SRAM, 256 K x 8, -40 to 85 degC, 36-Pin SOJ (SOJ-36), Pb-Free; Manufacturer: Integrated Silicon Solution Inc (ISSI); PartNumber: IS61LV2568L-10KLI; Density: 2M; Organization: 256K x 8; Packing: Tray / Tube; Speed (ns): 10
footprint ISSI-SOJ-36_N (SOJ, 36-Leads, Body 23.62x10.29mm, Pitch 1.27mm, IPC Medium Density)
pins: 1 A4 (in) "Address Input", 2 A3 (in) "Address Input", 3 A2 (in) "Address Input", 4 A1 (in) "Address Input", 5 A0 (in) "Address Input", 6 ~{CE} (in) "Chip Enable Input", 7 I/O0 (io) "Bidirectional Port", 8 I/O1 (io) "Bidirectional Port", 9 VDD (power) "Power", 10 GND (power) "Ground", 11 I/O2 (io) "Bidirectional Port", 12 I/O3 (io) "Bidirectional Port", 13 ~{WE} (in) "Write Enable Input", 14 A17 (in) "Address Input", 15 A16 (in) "Address Input", 16 A15 (in) "Address Input", 17 A14 (in) "Address Input", 18 A13 (in) "Address Input", 19 NC "No Connection", 20 NC "No Connection", 21 A12 (in) "Address Input", 22 A11 (in) "Address Input", 23 A10 (in) "Address Input", 24 A9 (in) "Address Input", 25 I/O4 (io) "Bidirectional Port", 26 I/O5 (io) "Bidirectional Port", 27 VDD (power) "Power", 28 GND (power) "Ground", 29 I/O6 (io) "Bidirectional Port", 30 I/O7 (io) "Bidirectional Port", 31 ~{OE} (in) "Output Enable Input", 32 A8 (in) "Address Input", 33 A7 (in) "Address Input", 34 A6 (in) "Address Input", 35 A5 (in) "Address Input", 36 NC "No Connection"

## IS61LV2568L-10KLI-TR
designator U?
2 M High Speed CMOS SRAM, 256 K x 8, -40 to 85 degC, 36-Pin SOJ (SOJ-36), Pb-Free; Manufacturer: Integrated Silicon Solution Inc (ISSI); PartNumber: IS61LV2568L-10KLI-TR; Density: 2M; Organization: 256K x 8; Packing: Tape & Reel; Speed (ns): 10
footprint ISSI-SOJ-36_N (SOJ, 36-Leads, Body 23.62x10.29mm, Pitch 1.27mm, IPC Medium Density)
pins: 1 A4 (in) "Address Input", 2 A3 (in) "Address Input", 3 A2 (in) "Address Input", 4 A1 (in) "Address Input", 5 A0 (in) "Address Input", 6 ~{CE} (in) "Chip Enable Input", 7 I/O0 (io) "Bidirectional Port", 8 I/O1 (io) "Bidirectional Port", 9 VDD (power) "Power", 10 GND (power) "Ground", 11 I/O2 (io) "Bidirectional Port", 12 I/O3 (io) "Bidirectional Port", 13 ~{WE} (in) "Write Enable Input", 14 A17 (in) "Address Input", 15 A16 (in) "Address Input", 16 A15 (in) "Address Input", 17 A14 (in) "Address Input", 18 A13 (in) "Address Input", 19 NC "No Connection", 20 NC "No Connection", 21 A12 (in) "Address Input", 22 A11 (in) "Address Input", 23 A10 (in) "Address Input", 24 A9 (in) "Address Input", 25 I/O4 (io) "Bidirectional Port", 26 I/O5 (io) "Bidirectional Port", 27 VDD (power) "Power", 28 GND (power) "Ground", 29 I/O6 (io) "Bidirectional Port", 30 I/O7 (io) "Bidirectional Port", 31 ~{OE} (in) "Output Enable Input", 32 A8 (in) "Address Input", 33 A7 (in) "Address Input", 34 A6 (in) "Address Input", 35 A5 (in) "Address Input", 36 NC "No Connection"

## IS61LV2568L-10T
designator U?
2 M High Speed CMOS SRAM, 256 K x 8, 0 to 70 degC, 44-Pin SOP (TSOP-2-44); Manufacturer: Integrated Silicon Solution Inc (ISSI); PartNumber: IS61LV2568L-10T; Density: 2M; Organization: 256K x 8; Packing: Tray / Tube; Speed (ns): 10
footprint ISSI-TSOP-2-44_N (SOP, 44-Leads, Body 18.5x10.3mm, Pitch 0.8mm, IPC Medium Density)
part A pins: 3 A4 (in) "Address Input", 4 A3 (in) "Address Input", 5 A2 (in) "Address Input", 6 A1 (in) "Address Input", 7 A0 (in) "Address Input", 8 ~{CE} (in) "Chip Enable Input", 9 I/O0 (io) "Bidirectional Port", 10 I/O1 (io) "Bidirectional Port", 11 VDD (power) "Power", 12 GND (power) "Ground", 13 I/O2 (io) "Bidirectional Port", 14 I/O3 (io) "Bidirectional Port", 15 ~{WE} (in) "Write Enable Input", 16 A17 (in) "Address Input", 17 A16 (in) "Address Input", 18 A15 (in) "Address Input", 19 A14 (in) "Address Input", 20 A13 (in) "Address Input", 27 A12 (in) "Address Input", 28 A11 (in) "Address Input", 29 A10 (in) "Address Input", 30 A9 (in) "Address Input", 31 I/O4 (io) "Bidirectional Port", 32 I/O5 (io) "Bidirectional Port", 33 VDD (power) "Power", 34 GND (power) "Ground", 35 I/O6 (io) "Bidirectional Port", 36 I/O7 (io) "Bidirectional Port", 37 ~{OE} (in) "Output Enable Input", 38 A8 (in) "Address Input", 39 A7 (in) "Address Input", 40 A6 (in) "Address Input", 41 A5 (in) "Address Input"
part B pins: 1 NC "No Connection", 2 NC "No Connection", 21 NC "No Connection", 22 NC "No Connection", 23 NC "No Connection", 24 NC "No Connection", 25 NC "No Connection", 26 NC "No Connection", 42 NC "No Connection", 43 NC "No Connection", 44 NC "No Connection"

## IS61LV2568L-10T-TR
designator U?
2 M High Speed CMOS SRAM, 256 K x 8, 0 to 70 degC, 44-Pin SOP (TSOP-2-44); Manufacturer: Integrated Silicon Solution Inc (ISSI); PartNumber: IS61LV2568L-10T-TR; Density: 2M; Organization: 256K x 8; Packing: Tape & Reel; Speed (ns): 10
footprint ISSI-TSOP-2-44_N (SOP, 44-Leads, Body 18.5x10.3mm, Pitch 0.8mm, IPC Medium Density)
part A pins: 3 A4 (in) "Address Input", 4 A3 (in) "Address Input", 5 A2 (in) "Address Input", 6 A1 (in) "Address Input", 7 A0 (in) "Address Input", 8 ~{CE} (in) "Chip Enable Input", 9 I/O0 (io) "Bidirectional Port", 10 I/O1 (io) "Bidirectional Port", 11 VDD (power) "Power", 12 GND (power) "Ground", 13 I/O2 (io) "Bidirectional Port", 14 I/O3 (io) "Bidirectional Port", 15 ~{WE} (in) "Write Enable Input", 16 A17 (in) "Address Input", 17 A16 (in) "Address Input", 18 A15 (in) "Address Input", 19 A14 (in) "Address Input", 20 A13 (in) "Address Input", 27 A12 (in) "Address Input", 28 A11 (in) "Address Input", 29 A10 (in) "Address Input", 30 A9 (in) "Address Input", 31 I/O4 (io) "Bidirectional Port", 32 I/O5 (io) "Bidirectional Port", 33 VDD (power) "Power", 34 GND (power) "Ground", 35 I/O6 (io) "Bidirectional Port", 36 I/O7 (io) "Bidirectional Port", 37 ~{OE} (in) "Output Enable Input", 38 A8 (in) "Address Input", 39 A7 (in) "Address Input", 40 A6 (in) "Address Input", 41 A5 (in) "Address Input"
part B pins: 1 NC "No Connection", 2 NC "No Connection", 21 NC "No Connection", 22 NC "No Connection", 23 NC "No Connection", 24 NC "No Connection", 25 NC "No Connection", 26 NC "No Connection", 42 NC "No Connection", 43 NC "No Connection", 44 NC "No Connection"

## IS61LV2568L-10TL
designator U?
2 M High Speed CMOS SRAM, 256 K x 8, 0 to 70 degC, 44-Pin SOP (TSOP-2-44), Pb-Free; Manufacturer: Integrated Silicon Solution Inc (ISSI); PartNumber: IS61LV2568L-10TL; Density: 2M; Organization: 256K x 8; Packing: Tray / Tube; Speed (ns): 10
footprint ISSI-TSOP-2-44_N (SOP, 44-Leads, Body 18.5x10.3mm, Pitch 0.8mm, IPC Medium Density)
part A pins: 3 A4 (in) "Address Input", 4 A3 (in) "Address Input", 5 A2 (in) "Address Input", 6 A1 (in) "Address Input", 7 A0 (in) "Address Input", 8 ~{CE} (in) "Chip Enable Input", 9 I/O0 (io) "Bidirectional Port", 10 I/O1 (io) "Bidirectional Port", 11 VDD (power) "Power", 12 GND (power) "Ground", 13 I/O2 (io) "Bidirectional Port", 14 I/O3 (io) "Bidirectional Port", 15 ~{WE} (in) "Write Enable Input", 16 A17 (in) "Address Input", 17 A16 (in) "Address Input", 18 A15 (in) "Address Input", 19 A14 (in) "Address Input", 20 A13 (in) "Address Input", 27 A12 (in) "Address Input", 28 A11 (in) "Address Input", 29 A10 (in) "Address Input", 30 A9 (in) "Address Input", 31 I/O4 (io) "Bidirectional Port", 32 I/O5 (io) "Bidirectional Port", 33 VDD (power) "Power", 34 GND (power) "Ground", 35 I/O6 (io) "Bidirectional Port", 36 I/O7 (io) "Bidirectional Port", 37 ~{OE} (in) "Output Enable Input", 38 A8 (in) "Address Input", 39 A7 (in) "Address Input", 40 A6 (in) "Address Input", 41 A5 (in) "Address Input"
part B pins: 1 NC "No Connection", 2 NC "No Connection", 21 NC "No Connection", 22 NC "No Connection", 23 NC "No Connection", 24 NC "No Connection", 25 NC "No Connection", 26 NC "No Connection", 42 NC "No Connection", 43 NC "No Connection", 44 NC "No Connection"

## IS61LV2568L-10TL-TR
designator U?
2 M High Speed CMOS SRAM, 256 K x 8, 0 to 70 degC, 44-Pin SOP (TSOP-2-44), Pb-Free; Manufacturer: Integrated Silicon Solution Inc (ISSI); PartNumber: IS61LV2568L-10TL-TR; Density: 2M; Organization: 256K x 8; Packing: Tape & Reel; Speed (ns): 10
footprint ISSI-TSOP-2-44_N (SOP, 44-Leads, Body 18.5x10.3mm, Pitch 0.8mm, IPC Medium Density)
part A pins: 3 A4 (in) "Address Input", 4 A3 (in) "Address Input", 5 A2 (in) "Address Input", 6 A1 (in) "Address Input", 7 A0 (in) "Address Input", 8 ~{CE} (in) "Chip Enable Input", 9 I/O0 (io) "Bidirectional Port", 10 I/O1 (io) "Bidirectional Port", 11 VDD (power) "Power", 12 GND (power) "Ground", 13 I/O2 (io) "Bidirectional Port", 14 I/O3 (io) "Bidirectional Port", 15 ~{WE} (in) "Write Enable Input", 16 A17 (in) "Address Input", 17 A16 (in) "Address Input", 18 A15 (in) "Address Input", 19 A14 (in) "Address Input", 20 A13 (in) "Address Input", 27 A12 (in) "Address Input", 28 A11 (in) "Address Input", 29 A10 (in) "Address Input", 30 A9 (in) "Address Input", 31 I/O4 (io) "Bidirectional Port", 32 I/O5 (io) "Bidirectional Port", 33 VDD (power) "Power", 34 GND (power) "Ground", 35 I/O6 (io) "Bidirectional Port", 36 I/O7 (io) "Bidirectional Port", 37 ~{OE} (in) "Output Enable Input", 38 A8 (in) "Address Input", 39 A7 (in) "Address Input", 40 A6 (in) "Address Input", 41 A5 (in) "Address Input"
part B pins: 1 NC "No Connection", 2 NC "No Connection", 21 NC "No Connection", 22 NC "No Connection", 23 NC "No Connection", 24 NC "No Connection", 25 NC "No Connection", 26 NC "No Connection", 42 NC "No Connection", 43 NC "No Connection", 44 NC "No Connection"

## IS61LV12824-8B
designator U?
3 M High Speed CMOS SRAM with 3.3 V Supply, 128 K x 24, 0 to 70 degC, 119-Pin BGA (PBGA-119); Manufacturer: Integrated Silicon Solution Inc (ISSI); PartNumber: IS61LV12824-8B; Density: 3M; Packing: Tray / Tube; Speed (ns): 8
footprint ISSI-PBGA-119-14000X22000DE_A (BGA, 119-Balls, Body 22x14mm, Pitch 1.27mm)
part A pins: A2 A11 (in) "Address Inputs", A3 A14 (in) "Address Inputs", A4 A15 (in) "Address Inputs", A5 A16 (in) "Address Inputs", A6 A4 (in) "Address Inputs", B2 A12 (in) "Address Inputs", B3 A13 (in) "Address Inputs", B4 ~{CE1} (in) "Chip Enable Input LOW", B5 A5 (in) "Address Input", B6 A3 (in) "Address Input", C1 I/O16 (io) "Data Inputs/Outputs", C3 CE2 (in) "Chip Enable Input HIGH", C5 ~{CE2} (in) "Chip Enable Input LOW", C7 I/O0 (io) "Data Inputs/Outputs", D1 I/O17 (io) "Data Inputs/Outputs", D7 I/O1 (io) "Data Inputs/Outputs", E1 I/O18 (io) "Data Inputs/Outputs", E7 I/O2 (io) "Data Inputs/Outputs", F1 I/O19 (io) "Data Inputs/Outputs", F7 I/O3 (io) "Data Inputs/Outputs", G1 I/O20 (io) "Data Inputs/Outputs", G7 I/O4 (io) "Data Inputs/Outputs", H1 I/O21 (io) "Data Inputs/Outputs", H7 I/O5 (io) "Data Inputs/Outputs", K1 I/O22 (io) "Data Inputs/Outputs", K7 I/O6 (io) "Data Inputs/Outputs", L1 I/O23 (io) "Data Inputs/Outputs", L7 I/O7 (io) "Data Inputs/Outputs", M1 I/O12 (io) "Data Inputs/Outputs", M7 I/O8 (io) "Data Inputs/Outputs", N1 I/O13 (io) "Data Inputs/Outputs", N7 I/O9 (io) "Data Inputs/Outputs", P1 I/O14 (io) "Data Inputs/Outputs", P7 I/O10 (io) "Data Inputs/Outputs", R1 I/O15 (io) "Data Inputs/Outputs", R7 I/O11 (io) "Data Inputs/Outputs", T2 A10 (in) "Address Inputs", T3 A8 (in) "Address Inputs", T4 ~{WE} (in) "Write Enable Input", T5 A0 (in) "Address Inputs", T6 A1 (in) "Address Inputs", U2 A9 (in) "Address Inputs", U3 A7 (in) "Address Inputs", U4 ~{OE} (in) "Output Enable Input", U5 A6 (in) "Address Inputs", U6 A2 (in) "Address Inputs"
part B pins: D2 VCCQ (power) "I/O Power", D3 GND (power) "Ground", D4 GND (power) "Ground", D5 GND (power) "Ground", D6 VCCQ (power) "I/O Power", E2 GND (power) "Ground", E3 VCC (power) "Power", E4 GND (power) "Ground", E5 VCC (power) "Power", E6 GND (power) "Ground", F2 VCCQ (power) "I/O Power", F3 GND (power) "Ground", F4 GND (power) "Ground", F5 GND (power) "Ground", F6 VCCQ (power) "I/O Power", G2 GND (power) "Ground", G3 VCC (power) "Power", G4 GND (power) "Ground", G5 VCC (power) "Power", G6 GND (power) "Ground", H2 VCCQ (power) "I/O Power", H3 GND (power) "Ground", H4 GND (power) "Ground", H5 GND (power) "Ground", H6 VCCQ (power) "I/O Power", J1 VCCQ (power) "I/O Power", J2 GND (power) "Ground", J3 VCC (power) "Power", J4 GND (power) "Ground", J5 VCC (power) "Power", J6 GND (power) "Ground", J7 VCCQ (power) "I/O Power", K2 VCCQ (power) "I/O Power", K3 GND (power) "Ground", K4 GND (power) "Ground", K5 GND (power) "Ground", K6 VCCQ (power) "I/O Power", L2 GND (power) "Ground", L3 VCC (power) "Power", L4 GND (power) "Ground", L5 VCC (power) "Power", L6 GND (power) "Ground", M2 VCCQ (power) "I/O Power", M3 GND (power) "Ground", M4 GND (power) "Ground", M5 GND (power) "Ground", M6 VCCQ (power) "I/O Power", N2 GND (power) "Ground", N3 VCC (power) "Power", N4 GND (power) "Ground", N5 VCC (power) "Power", N6 GND (power) "Ground", P2 VCCQ (power) "I/O Power", P3 GND (power) "Ground", P4 GND (power) "Ground", P5 GND (power) "Ground", P6 VCCQ (power) "I/O Power"
part C pins: A1 NC "No Connection", A7 NC "No Connection", B1 NC "No Connection", B7 NC "No Connection", C2 NC "No Connection", C4 NC "No Connection", C6 NC "No Connection", R2 NC "No Connection", R3 NC "No Connection", R4 NC "No Connection", R5 NC "No Connection", R6 NC "No Connection", T1 NC "No Connection", T7 NC "No Connection", U1 NC "No Connection", U7 NC "No Connection"

## IS61LV12824-8B-TR
designator U?
3 M High Speed CMOS SRAM with 3.3 V Supply, 128 K x 24, 0 to 70 degC, 119-Pin BGA (PBGA-119); Manufacturer: Integrated Silicon Solution Inc (ISSI); PartNumber: IS61LV12824-8B-TR; Density: 3M; Packing: Tape & Reel; Speed (ns): 8
footprint ISSI-PBGA-119-14000X22000DE_A (BGA, 119-Balls, Body 22x14mm, Pitch 1.27mm)
part A pins: A2 A11 (in) "Address Inputs", A3 A14 (in) "Address Inputs", A4 A15 (in) "Address Inputs", A5 A16 (in) "Address Inputs", A6 A4 (in) "Address Inputs", B2 A12 (in) "Address Inputs", B3 A13 (in) "Address Inputs", B4 ~{CE1} (in) "Chip Enable Input LOW", B5 A5 (in) "Address Input", B6 A3 (in) "Address Input", C1 I/O16 (io) "Data Inputs/Outputs", C3 CE2 (in) "Chip Enable Input HIGH", C5 ~{CE2} (in) "Chip Enable Input LOW", C7 I/O0 (io) "Data Inputs/Outputs", D1 I/O17 (io) "Data Inputs/Outputs", D7 I/O1 (io) "Data Inputs/Outputs", E1 I/O18 (io) "Data Inputs/Outputs", E7 I/O2 (io) "Data Inputs/Outputs", F1 I/O19 (io) "Data Inputs/Outputs", F7 I/O3 (io) "Data Inputs/Outputs", G1 I/O20 (io) "Data Inputs/Outputs", G7 I/O4 (io) "Data Inputs/Outputs", H1 I/O21 (io) "Data Inputs/Outputs", H7 I/O5 (io) "Data Inputs/Outputs", K1 I/O22 (io) "Data Inputs/Outputs", K7 I/O6 (io) "Data Inputs/Outputs", L1 I/O23 (io) "Data Inputs/Outputs", L7 I/O7 (io) "Data Inputs/Outputs", M1 I/O12 (io) "Data Inputs/Outputs", M7 I/O8 (io) "Data Inputs/Outputs", N1 I/O13 (io) "Data Inputs/Outputs", N7 I/O9 (io) "Data Inputs/Outputs", P1 I/O14 (io) "Data Inputs/Outputs", P7 I/O10 (io) "Data Inputs/Outputs", R1 I/O15 (io) "Data Inputs/Outputs", R7 I/O11 (io) "Data Inputs/Outputs", T2 A10 (in) "Address Inputs", T3 A8 (in) "Address Inputs", T4 ~{WE} (in) "Write Enable Input", T5 A0 (in) "Address Inputs", T6 A1 (in) "Address Inputs", U2 A9 (in) "Address Inputs", U3 A7 (in) "Address Inputs", U4 ~{OE} (in) "Output Enable Input", U5 A6 (in) "Address Inputs", U6 A2 (in) "Address Inputs"
part B pins: D2 VCCQ (power) "I/O Power", D3 GND (power) "Ground", D4 GND (power) "Ground", D5 GND (power) "Ground", D6 VCCQ (power) "I/O Power", E2 GND (power) "Ground", E3 VCC (power) "Power", E4 GND (power) "Ground", E5 VCC (power) "Power", E6 GND (power) "Ground", F2 VCCQ (power) "I/O Power", F3 GND (power) "Ground", F4 GND (power) "Ground", F5 GND (power) "Ground", F6 VCCQ (power) "I/O Power", G2 GND (power) "Ground", G3 VCC (power) "Power", G4 GND (power) "Ground", G5 VCC (power) "Power", G6 GND (power) "Ground", H2 VCCQ (power) "I/O Power", H3 GND (power) "Ground", H4 GND (power) "Ground", H5 GND (power) "Ground", H6 VCCQ (power) "I/O Power", J1 VCCQ (power) "I/O Power", J2 GND (power) "Ground", J3 VCC (power) "Power", J4 GND (power) "Ground", J5 VCC (power) "Power", J6 GND (power) "Ground", J7 VCCQ (power) "I/O Power", K2 VCCQ (power) "I/O Power", K3 GND (power) "Ground", K4 GND (power) "Ground", K5 GND (power) "Ground", K6 VCCQ (power) "I/O Power", L2 GND (power) "Ground", L3 VCC (power) "Power", L4 GND (power) "Ground", L5 VCC (power) "Power", L6 GND (power) "Ground", M2 VCCQ (power) "I/O Power", M3 GND (power) "Ground", M4 GND (power) "Ground", M5 GND (power) "Ground", M6 VCCQ (power) "I/O Power", N2 GND (power) "Ground", N3 VCC (power) "Power", N4 GND (power) "Ground", N5 VCC (power) "Power", N6 GND (power) "Ground", P2 VCCQ (power) "I/O Power", P3 GND (power) "Ground", P4 GND (power) "Ground", P5 GND (power) "Ground", P6 VCCQ (power) "I/O Power"
part C pins: A1 NC "No Connection", A7 NC "No Connection", B1 NC "No Connection", B7 NC "No Connection", C2 NC "No Connection", C4 NC "No Connection", C6 NC "No Connection", R2 NC "No Connection", R3 NC "No Connection", R4 NC "No Connection", R5 NC "No Connection", R6 NC "No Connection", T1 NC "No Connection", T7 NC "No Connection", U1 NC "No Connection", U7 NC "No Connection"

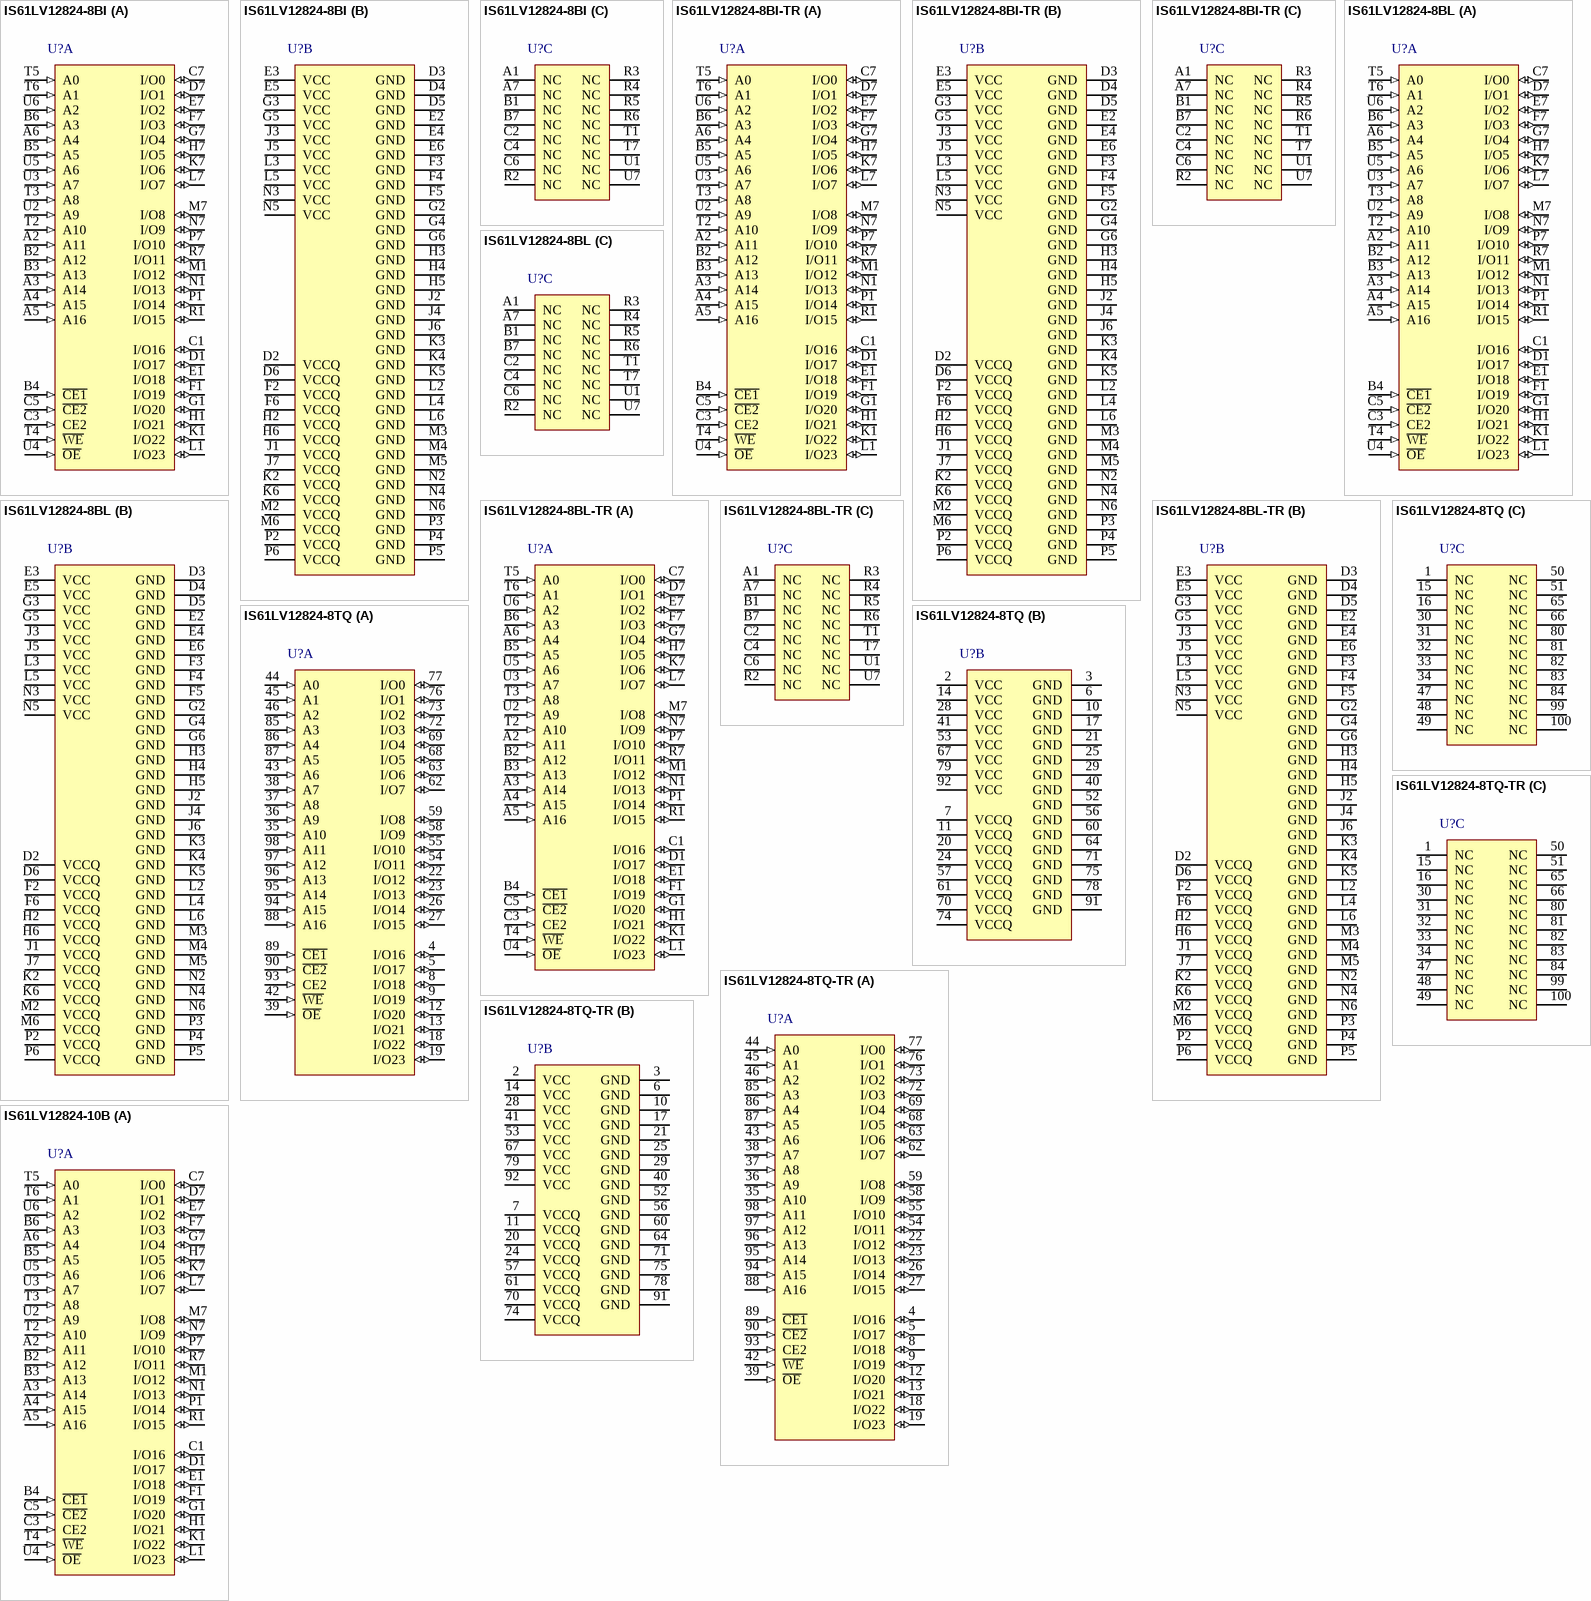
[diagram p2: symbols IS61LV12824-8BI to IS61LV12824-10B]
